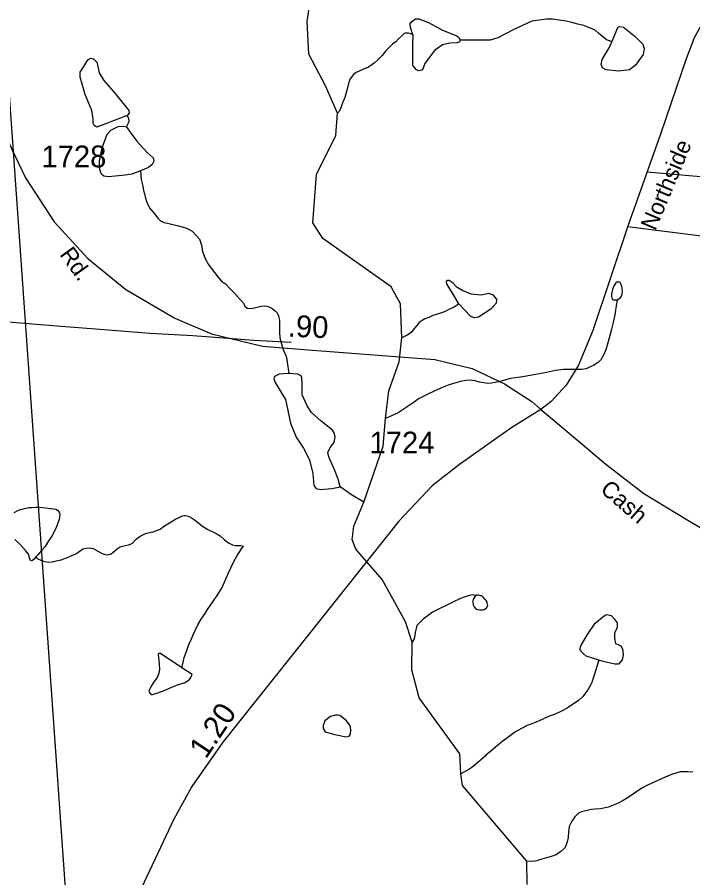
# Model space of a CAD drawing. Extents: x 2056842 to 2160602, y 826753 to 1016856.
# Drawn here: x 2079610 to 2083484, y 850234 to 855171 of the extents above; entities that cross this region are included whole.
import ezdxf

# ---------------------------------------------------------------- set-up
doc = ezdxf.new("R2010")
doc.units = 0
for name, color, linetype in [('Exist Hydrographic Creek Single Shore', 7, 'Continuous'), ('Exist Hydrographic Misc Water Feature', 7, 'Continuous'), ('Exist Railroad Mainline', 7, 'Continuous'), ('Exist Road Non-System Type 51', 7, 'Continuous'), ('Exist Road Secondary Mileage Hundredths English Label', 7, 'Continuous'), ('Exist Road Secondary Type 51 Attributed', 7, 'Continuous'), ('Exist Road Secondary Type 51 Label', 7, 'Continuous'), ('Exist Road Secondary Type 51 Number Label', 7, 'Continuous'), ('Exist Utilities Electrical Transmission Line', 7, 'Continuous')]:
    doc.layers.add(name, color=color, linetype=linetype)

msp = doc.modelspace()

# ---------------------------------------------------------------- linework, layer by layer
at = {"layer": 'Exist Hydrographic Creek Single Shore'}
msp.add_lwpolyline([(2082533.2, 850195.2), (2082532.2, 850329.7), (2082164, 850762.4), (2082153.5, 850829.6), (2082147.3, 850944.7), (2081915.7, 851265.3), (2081872.8, 851426.8), (2081874.3, 851585.1), (2081836.3, 851702.5), (2081702.4, 851944.7), (2081551.4, 852119.8), (2081531.6, 852175.2), (2081540.8, 852250.2), (2081597.5, 852388.6), (2081708.3, 852709.1), (2081722.5, 852867.7), (2081741.3, 853026.8), (2081799.4, 853192.9), (2081816.1, 853331), (2081808, 853526.1), (2081754, 853623.7), (2081363.2, 853900.8), (2081305.4, 853990.6), (2081325.6, 854269.1), (2081436.2, 854493.2), (2081446.4, 854621.1), (2081377.4, 854776.6), (2081283.1, 854958.6), (2081272.6, 855145.8), (2081292.3, 855273.8)], dxfattribs=at)
at = {"layer": 'Exist Hydrographic Misc Water Feature'}
for points in [[(2081879, 855070.5), (2081864.7, 855112.1), (2081863.4, 855133.2), (2081872.6, 855146.4), (2081893.7, 855162.2), (2081912.1, 855162.2), (2081968.8, 855141.1), (2082049.1, 855096.3), (2082130.8, 855064.7), (2082144, 855052.8), (2082147.9, 855043.6)], [(2083018.7, 855029.1), (2083007, 855035.8), (2082988.8, 855041.8), (2082973, 855053.6), (2082956.6, 855067.8), (2082942.4, 855079.6), (2082926.6, 855093.8), (2082906.6, 855103.8), (2082882.6, 855113.5), (2082858.4, 855123.3), (2082824.3, 855131.2), (2082790.5, 855141.3), (2082758.5, 855149), (2082718.3, 855153), (2082678.5, 855159), (2082644.5, 855158.9), (2082604.3, 855154.8), (2082560.4, 855148.5), (2082458.2, 855100.3), (2082366, 855052.8), (2082321.2, 855038.3), (2082214.5, 855039.6), (2082149.2, 855038.3)], [(2083018.7, 855029.1), (2083052.9, 855112.1), (2083066.1, 855117.4), (2083087.2, 855113.5), (2083153, 855059.4), (2083196.5, 855015.9), (2083204.4, 854990.9), (2083199.1, 854956.6), (2083154.4, 854895.9), (2083120.1, 854868.3), (2083058.2, 854861.7), (2082987, 854869.6), (2082966, 854881.4), (2082958, 854899.9), (2082964.6, 854928.9), (2083004.2, 854994.8), (2083018.7, 855029.1)], [(2081880.9, 855069.3), (2081879, 855070.5), (2081866.7, 855076.4), (2081853, 855080.1), (2081836.8, 855080.1), (2081828.8, 855078.1), (2081813, 855062.2), (2081796.8, 855046), (2081780.8, 855030.2), (2081762.8, 855015.9), (2081743.3, 854997.7), (2081721.4, 854975.9), (2081703.3, 854951.8), (2081679.3, 854927.9), (2081657.2, 854907.7), (2081623.5, 854883.6), (2081591.8, 854871.4), (2081553.4, 854853.3), (2081537.8, 854841.4), (2081519.4, 854817.4), (2081511.6, 854799.1), (2081505.6, 854773.2), (2081498.1, 854745.2), (2081488, 854711), (2081475.9, 854679.2), (2081464.4, 854645.2), (2081454, 854628.9), (2081446.4, 854621.1)], [(2082147.9, 855043.6), (2082149.2, 855038.3), (2082146.6, 855029.1), (2082133.4, 855023.8), (2082090, 855021.2), (2082047.8, 855013.3), (2082003, 854979), (2081947.7, 854905.2), (2081933.2, 854868.3), (2081914.7, 854863), (2081898.9, 854869.6), (2081879.2, 854893.3), (2081879.2, 855014.6), (2081880.9, 855069.3)], [(2080241.4, 854606.7), (2080180.8, 854584.3), (2080092.5, 854550), (2080066.2, 854540.8), (2080051.7, 854548.7), (2080046.4, 854561.9), (2080046.4, 854586.9), (2080037.2, 854635.7), (2079999, 854726.7), (2079971.3, 854826.9), (2079971.3, 854855.9), (2079992.4, 854888.8), (2080016.1, 854925.7), (2080033.3, 854935), (2080047.7, 854932.3), (2080066.2, 854912.6), (2080080.7, 854851.9), (2080107, 854807.1), (2080159.7, 854746.4), (2080203.2, 854695), (2080250.6, 854635.7), (2080252, 854621.2), (2080241.4, 854606.7)], [(2080236.1, 854542.6), (2080252, 854572.4), (2080249.3, 854589.6), (2080241.4, 854606.7)], [(2080317.8, 854289.5), (2080267.8, 854271.1), (2080229.6, 854264.5), (2080133.4, 854255.3), (2080107, 854259.2), (2080093.9, 854269.8), (2080083.3, 854296.1), (2080082, 854344.9), (2080096.5, 854421.4), (2080125.5, 854499.1), (2080146.6, 854522.9), (2080190, 854544), (2080219, 854545.3), (2080236.1, 854542.6)], [(2080236.1, 854542.6), (2080258.5, 854511), (2080296.7, 854459.6), (2080356, 854395), (2080389, 854363.4), (2080394.2, 854344.9), (2080383.7, 854326.5), (2080362.6, 854309.3), (2080317.8, 854289.5)], [(2080317.8, 854289.5), (2080321.8, 854239.4), (2080329.9, 854201.7), (2080333.8, 854177.5), (2080339.9, 854157.6), (2080346.1, 854133.5), (2080354.1, 854109.6), (2080368.2, 854077.8), (2080386.3, 854056), (2080397.9, 854042), (2080416, 854017.8), (2080432.6, 854001.9), (2080450.2, 853993.9), (2080472.2, 853990.2), (2080510.5, 853980.4), (2080534.1, 853974.3), (2080556.7, 853968.5), (2080580.2, 853960.4), (2080600.7, 853950.4), (2080614.3, 853942.7), (2080638.9, 853916.6), (2080654.7, 853896.8), (2080668.8, 853856.5)], [(2080668.8, 853856.5), (2080669, 853852.8), (2080672.7, 853826.7), (2080688.9, 853782.9), (2080707.2, 853752.9), (2080723.2, 853731), (2080761.1, 853681), (2080781.4, 853656.9), (2080805.4, 853641.1), (2080833.7, 853611.2), (2080855.6, 853587.2), (2080885.6, 853555.5), (2080907.5, 853529.4), (2080915.5, 853513.6), (2080929.6, 853501.7), (2080945.8, 853499.7), (2080962, 853501.7), (2080986, 853507.8), (2081009.8, 853513.9), (2081026, 853515.9), (2081041.8, 853513.9), (2081057.8, 853507.9), (2081071.7, 853500), (2081092, 853484), (2081099.8, 853474.3), (2081108, 853458), (2081114.2, 853430.3), (2081114.2, 853400.3), (2081114.2, 853364.2), (2081116.4, 853332.2), (2081126.5, 853290.1), (2081136.3, 853258.2), (2081148.6, 853234.4), (2081154.4, 853218.5), (2081166.7, 853127.4)], [(2082143, 853527.3), (2082112.5, 853577.5), (2082073, 853640.8), (2082071.6, 853655.3), (2082078.2, 853663.2), (2082087.5, 853663.2), (2082104.6, 853650.1), (2082127, 853626.3), (2082165.2, 853603.9), (2082211.3, 853584.1), (2082270.6, 853577.5), (2082314.1, 853586.8), (2082336.5, 853577.5), (2082358.9, 853553.8), (2082356.2, 853530.1), (2082325.9, 853495.8), (2082254.8, 853449.7), (2082229.7, 853445.7), (2082208.7, 853456.3), (2082143, 853527.3)], [(2083049.3, 853550), (2083053.6, 853552.2), (2083061.4, 853556.3), (2083069.2, 853562.4), (2083075.3, 853570.4), (2083079.4, 853582.4), (2083079, 853588.5), (2083081.3, 853598.3), (2083079, 853614), (2083077.4, 853626.1), (2083072.9, 853638.1), (2083071, 853642.1), (2083066.9, 853648.4), (2083063, 853650.2), (2083055, 853650.2), (2083051.1, 853650.3), (2083046.8, 853650.2), (2083043.3, 853646.3), (2083039.2, 853642), (2083033.3, 853632), (2083027.1, 853620.3), (2083023.2, 853608.3), (2083019.3, 853594.3), (2083017.3, 853580), (2083017.5, 853568.2), (2083019.1, 853560.3), (2083021.6, 853554.2), (2083025.5, 853552), (2083029.4, 853550.2), (2083039.6, 853550.3), (2083049.3, 853550)], [(2083049.3, 853550), (2083045.8, 853528.2), (2083037.6, 853464.1), (2083031.6, 853438.3), (2083025.9, 853412), (2083018.1, 853380.3), (2083008.3, 853344), (2082996.2, 853302), (2082986.3, 853268.2), (2082974.4, 853235.9), (2082956.4, 853205.8), (2082940.4, 853190), (2082916.6, 853173.7), (2082890.6, 853163.8), (2082872.3, 853153.6), (2082848.2, 853150.6), (2082788.9, 853150.6), (2082741.5, 853150.6), (2082696.8, 853143.3), (2082644, 853132.1), (2082582, 853120.2), (2082509.6, 853107.1), (2082438.6, 853098.5), (2082404.6, 853088.2), (2082371, 853079.9), (2082328.9, 853072.1), (2082306.8, 853069.8), (2082285, 853073.9), (2082261.1, 853077.9), (2082235.2, 853083.9), (2082206.9, 853087.7), (2082182.7, 853087.4), (2082151.1, 853081.6), (2082111, 853069.5), (2082081.2, 853059.3), (2082043.1, 853045.2), (2082005.1, 853027), (2081957.4, 853004.7), (2081911.2, 852980.8), (2081885.4, 852962.8), (2081857.7, 852942.7), (2081795, 852901.9), (2081722.5, 852867.7)], [(2082143, 853527.3), (2082127.8, 853515.3), (2082111.6, 853505.1), (2082088, 853495.3), (2082059.5, 853481), (2082032, 853470.9), (2081993.9, 853458.9), (2081970.1, 853448.7), (2081947.9, 853440.7), (2081931.7, 853430.9), (2081915.7, 853418.8), (2081902, 853402.6), (2081887.9, 853386.5), (2081880.3, 853376.6), (2081870.2, 853364.4), (2081855.9, 853352.4), (2081846.4, 853346.5), (2081816.1, 853331)], [(2081166.7, 853127.4), (2081111.3, 853123.4), (2081086.3, 853110.2), (2081082.4, 853097), (2081088.9, 853074.6), (2081148.2, 852977.1), (2081162.7, 852915.1), (2081177.2, 852841.3), (2081210.2, 852762.2), (2081252.3, 852698.9), (2081286.6, 852630.8), (2081305, 852553), (2081311.6, 852484.4), (2081324.8, 852467.3), (2081348.5, 852460.7), (2081414.4, 852467.3), (2081461.8, 852475.7)], [(2081461.8, 852475.7), (2081451.3, 852521.4), (2081430.2, 852574.1), (2081397.2, 852647.9), (2081392, 852673), (2081403.8, 852702), (2081427.5, 852731), (2081434.1, 852763.9), (2081430.2, 852782.4), (2081417, 852800.8), (2081353.8, 852853.6), (2081298.4, 852902.3), (2081272.1, 852941.9), (2081244.4, 853003.8), (2081243.1, 853069.8), (2081241.8, 853102.7), (2081237.8, 853112.9), (2081219.4, 853123.4), (2081166.7, 853127.4)], [(2081597.5, 852388.6), (2081526.3, 852430.9), (2081461.8, 852475.7)], [(2079593.5, 852329.6), (2079617.5, 852341.8), (2079651.6, 852351.6), (2079677.6, 852357.8), (2079695.4, 852357.9), (2079715.3, 852359.8), (2079737.5, 852360.1), (2079753.3, 852358.1), (2079773.4, 852356.3), (2079801.7, 852352), (2079819.5, 852350.1), (2079831.6, 852348.3), (2079841.6, 852342.3), (2079851.5, 852330.3), (2079853.7, 852320.2), (2079853.5, 852304.4), (2079851.7, 852288.4), (2079843.7, 852268.1), (2079830, 852234.1), (2079808, 852194), (2079790.2, 852166.3), (2079770.3, 852134), (2079750.2, 852111.9), (2079726.4, 852083.8), (2079716.1, 852074)], [(2079716.1, 852074), (2079728.5, 852064), (2079746.3, 852056), (2079766.6, 852048.1), (2079792.4, 852044.2), (2079810.7, 852046.3), (2079834.5, 852052.5), (2079862.8, 852058.3), (2079902.5, 852072.6), (2079920.4, 852080.4), (2079946.6, 852092.7), (2079958.1, 852100.6), (2079986.2, 852120.7), (2080006.5, 852125), (2080022.5, 852127), (2080046.5, 852122.9), (2080072.3, 852106.9), (2080098, 852093.2), (2080114.4, 852089.1), (2080128.5, 852087), (2080138.1, 852089.2), (2080148.2, 852091.3), (2080158, 852099.5), (2080184.3, 852121.5), (2080200.1, 852131.4), (2080214.2, 852135.3), (2080247.8, 852143.6), (2080260.2, 852147.8), (2080270.4, 852153.6), (2080289.9, 852173.7), (2080304.2, 852185.7), (2080320, 852195.9), (2080337.7, 852205.8), (2080353.7, 852209.9), (2080377.6, 852216), (2080390, 852218.2), (2080404.1, 852224.1), (2080429.9, 852234), (2080453.9, 852252.3), (2080483.7, 852270.1), (2080517.5, 852290.5), (2080541.7, 852302.3), (2080557.9, 852310.4), (2080567.5, 852312.6), (2080573.5, 852312.5), (2080583.3, 852310.6), (2080595.4, 852306.7), (2080609.6, 852298.9), (2080631.9, 852282.9), (2080671.7, 852251), (2080703.7, 852231.1), (2080751.9, 852209.2), (2080773.6, 852195.3), (2080798, 852173.3), (2080821.8, 852155.6), (2080844.1, 852143.7), (2080862.2, 852139.7), (2080890.3, 852139.5), (2080908.3, 852135.6)], [(2079716.1, 852074), (2079708.6, 852063.8), (2079698.3, 852054), (2079692.6, 852052.1), (2079684.6, 852055.7), (2079680.7, 852069.7), (2079674.1, 852089.7), (2079660.6, 852109.7), (2079642.3, 852127.8), (2079624.3, 852149.7), (2079596.4, 852173.7)], [(2080554.2, 851438.6), (2080558.1, 851452.6), (2080564.2, 851478.8), (2080568.1, 851496.5), (2080581.9, 851536.6), (2080594, 851572.5), (2080609.8, 851604.6), (2080619.8, 851626.6), (2080631.5, 851652.9), (2080645.2, 851684.9), (2080665.1, 851717.1), (2080687.5, 851749), (2080701.2, 851772.9), (2080731.2, 851817.1), (2080761.1, 851859.2), (2080784.7, 851899.4), (2080802.9, 851939.3), (2080822.6, 851983.4), (2080852.3, 852047.4), (2080870, 852079.7), (2080896, 852121.6), (2080900.1, 852127.5), (2080908.3, 852135.6)], [(2082243.4, 851854.1), (2082238.1, 851852.6), (2082219.4, 851856.1), (2082195.4, 851852.1), (2082173.7, 851844), (2082151.6, 851836), (2082111.6, 851817.7), (2082073.6, 851797.5), (2082029.8, 851775.7), (2081991.8, 851757.5), (2081966, 851737.6), (2081939.9, 851719.1), (2081922.1, 851701.2), (2081902.2, 851681.1), (2081897.9, 851663.1), (2081892.2, 851641.2), (2081890.5, 851623.2), (2081886.2, 851605.2), (2081874.3, 851585.1)], [(2082243.4, 851854.1), (2082238.1, 851852.6), (2082231.5, 851844.2), (2082225.6, 851834.1), (2082223.7, 851827.9), (2082221.3, 851816.1), (2082223.7, 851810), (2082223.7, 851800.3), (2082229.9, 851788), (2082237.5, 851778.4), (2082243.6, 851774.2), (2082251.8, 851772.1), (2082260, 851770.1), (2082267.6, 851770.5), (2082277.9, 851770.2), (2082287.5, 851772.4), (2082293.7, 851776.3), (2082299.6, 851778.3), (2082305.6, 851788.3), (2082307.8, 851794.5), (2082305.3, 851808.2), (2082305.6, 851814.3), (2082299.6, 851824.5), (2082293.5, 851830.3), (2082281.6, 851844.3), (2082273.8, 851850.3), (2082267.2, 851852.1), (2082255.3, 851854.4), (2082243.4, 851854.1)], [(2082944, 851482.2), (2082872.8, 851505.9), (2082853, 851521.7), (2082838.6, 851540.2), (2082839.9, 851560), (2082880.7, 851628.5), (2082924.2, 851694.4), (2082978.2, 851739.2), (2082991.4, 851743.2), (2083016.4, 851737.9), (2083033.5, 851719.5), (2083050.7, 851695.7), (2083050.7, 851669.4), (2083034.9, 851637.7), (2083034.9, 851607.4), (2083041.4, 851577.1), (2083059.9, 851569.2), (2083070.4, 851563.9), (2083079.7, 851546.8), (2083083.6, 851512.5), (2083078.3, 851484.8), (2083057.3, 851458.4), (2083036.2, 851458.4), (2082970.3, 851474.3), (2082944, 851482.2)], [(2080554.2, 851438.6), (2080432.2, 851520.4), (2080427.9, 851520.2), (2080421.9, 851520.3), (2080417.8, 851516), (2080418.2, 851510.3), (2080421.9, 851482.2), (2080424.2, 851456.3), (2080426.7, 851428.3), (2080422.6, 851408.2), (2080416.4, 851390.1), (2080406.6, 851374.1), (2080392.6, 851354.3), (2080382.8, 851338), (2080374.8, 851326.2), (2080369, 851314.1), (2080364.9, 851302.1), (2080366.8, 851298.2), (2080374.8, 851288), (2080380.9, 851285.9), (2080386.5, 851284.2), (2080416.6, 851294.3), (2080452.5, 851308.3), (2080496.4, 851326.4), (2080528.6, 851340.6), (2080572.4, 851354.7), (2080586.6, 851362.7), (2080598.5, 851370.6), (2080606.5, 851382.8), (2080612.2, 851396.9), (2080614.1, 851400.7), (2080554.2, 851438.6)], [(2082944, 851482.2), (2082904.5, 851354.1), (2082897.9, 851338.1), (2082882.2, 851312.1), (2082870.3, 851296), (2082852.4, 851273.9), (2082826.6, 851247.9), (2082782.7, 851219.6), (2082762.8, 851207.6), (2082730.8, 851189.3), (2082695.1, 851173.2), (2082656.6, 851159.2), (2082620.9, 851141.1), (2082577, 851123), (2082533.2, 851106.9), (2082501.2, 851090.7), (2082463, 851068.5), (2082431.4, 851044.4), (2082395.2, 851018.3), (2082365.2, 850994.4), (2082323.6, 850958.1), (2082299.8, 850938.2), (2082291.6, 850930.1), (2082237.7, 850883.9), (2082215.9, 850866.1), (2082199.9, 850853.9), (2082153.5, 850829.6)], [(2081435.1, 851166.7), (2081407.1, 851158.9), (2081374.5, 851133.5), (2081363.5, 851108), (2081363.5, 851089.2), (2081375.8, 851070.9), (2081430.5, 851055.9), (2081496.3, 851042.9), (2081512.6, 851046.8), (2081521, 851057.9), (2081523.6, 851083.3), (2081519.1, 851106.7), (2081495.6, 851136.1), (2081460.5, 851164.1), (2081448.8, 851167.3), (2081435.1, 851166.7)], [(2083484, 850839.8), (2083453.6, 850841.6), (2083412, 850841.4), (2083367.5, 850827.4), (2083325.7, 850811.5), (2083261.9, 850783), (2083224.2, 850765.2), (2083192.2, 850746.9), (2083150.2, 850718.8), (2083118.4, 850698.9), (2083084.5, 850676.8), (2083056.7, 850662.4), (2083024, 850648.6), (2082998.2, 850638.4), (2082956.4, 850630.1), (2082924.2, 850628.1), (2082900.6, 850626), (2082846.3, 850611.9), (2082828.4, 850604), (2082806.9, 850583.8), (2082790.5, 850557.8), (2082774.9, 850527.7), (2082770.8, 850497.6), (2082769, 850463.8), (2082762.8, 850439.5), (2082751.1, 850407.6), (2082727.1, 850383.6), (2082699.5, 850365.5), (2082665.6, 850353.2), (2082637.5, 850345.3), (2082605.5, 850337.2), (2082589.5, 850331), (2082563.5, 850326.9), (2082532.2, 850329.7)]]:
    msp.add_lwpolyline(points, dxfattribs=at)
at = {"layer": 'Exist Railroad Mainline'}
msp.add_lwpolyline([(2081181.8, 853304.7), (2080967.8, 853316.1), (2080795.7, 853329.8), (2080617.5, 853343.5), (2080371.6, 853357), (2080133.4, 853374.5), (2079837.4, 853397.8), (2079559.3, 853421.3)], dxfattribs=at)
at = {"layer": 'Exist Road Non-System Type 51'}
for points in [[(2083221.3, 854283.4), (2083616.1, 854250), (2084368, 854196), (2084772, 854159.6), (2084904.9, 854153.4), (2085102.2, 854261.5), (2085249.7, 854267.7), (2085380.6, 854238.6), (2085440.8, 854246.9), (2085509.3, 854224.1), (2085586.2, 854190.8)], [(2083109.9, 853969.7), (2083533.1, 853917.5), (2083605.8, 853888.4), (2083626.5, 853842.7), (2083624.4, 853759.5), (2083599.5, 853649.4), (2083599.5, 853599.5), (2083653.5, 853568.3)]]:
    msp.add_lwpolyline(points, dxfattribs=at)
at = {"layer": 'Exist Road Secondary Type 51 Attributed'}
for points in [[(2087449.7, 857409.9), (2087040.5, 857169.9), (2086532.2, 856865.9), (2086157.3, 856642.3), (2085516.1, 856263.7), (2085113.7, 856080.3), (2084712.8, 855964.9), (2084408, 855887.5), (2084270.9, 855828.3), (2084122.4, 855729.6), (2083844.7, 855515), (2083712.8, 855397.5), (2083612.6, 855268.2), (2083491.1, 855053), (2083445.4, 854932.5), (2083298.4, 854500.7), (2083113.1, 853978.5), (2082911.1, 853374.3), (2082828.5, 853174.2), (2082757.9, 853058.9), (2082670.7, 852966.4), (2082612.5, 852919.6)], [(2079112.9, 855248.1), (2079221.6, 855119.8), (2079309.3, 854976.9), (2079389.3, 854833.5), (2079451.6, 854689.1), (2079577.8, 854418.4), (2079657.8, 854249), (2079822.4, 853997), (2080014.5, 853787), (2080233.1, 853607.8), (2080513.5, 853443.6), (2080723.7, 853353.7), (2081016.6, 853284.1), (2081253.4, 853264.3), (2081729.5, 853228.5), (2082003.7, 853206.7), (2082219.2, 853156.3), (2082405, 853066.9), (2082561.3, 852965.6), (2082612.5, 852919.6)], [(2082612.5, 852919.6), (2082446.6, 852816.4), (2082145.4, 852604.4), (2081989.6, 852481.8), (2081798.6, 852280.2), (2081276.2, 851624.5), (2080789.2, 851012.4), (2080610.6, 850756.8), (2080508.8, 850569.7), (2080277.2, 850078.2), (2080163, 849773.9), (2080132.8, 849669.4), (2080123.5, 849627.1), (2080070.5, 849339.3), (2080035.2, 849218.7), (2079968.8, 849116.9), (2079875.3, 848998.4), (2079759, 848915.3), (2079640.6, 848869.6), (2079491.1, 848832.2), (2079177.5, 848836.3), (2078779.7, 848824.9)], [(2082612.5, 852919.6), (2082763.6, 852794.4), (2082984.8, 852607.3), (2083202.4, 852438.5), (2083454.7, 852285.7), (2084155.2, 851870.6), (2084318.2, 851764.6), (2084438.1, 851649.7), (2084509.8, 851537.5), (2084548.2, 851426.3), (2084569.5, 851319.8), (2084563.3, 851187.8), (2084529, 851055.8), (2084380, 850696.8), (2084308.3, 850528.5), (2084228.9, 850350.2), (2084199.8, 850245.3), (2084187.4, 850116.4)]]:
    msp.add_lwpolyline(points, dxfattribs=at)
at = {"layer": 'Exist Utilities Electrical Transmission Line'}
msp.add_lwpolyline([(2079289.6, 845905.8), (2079948.4, 849305.4), (2079483.2, 855866.2), (2080101, 858353.8), (2081583.8, 864201.8), (2082616, 868304.1), (2080660.7, 871519), (2079505, 873046.5), (2077150, 875999.6), (2076168.7, 877076.1), (2079417.8, 882691.3), (2077477.1, 888146.6), (2075950.7, 892161.6), (2073748.3, 895216.6), (2070106.7, 900031.7)], dxfattribs=at)

# ---------------------------------------------------------------- texts
at = {"layer": 'Exist Road Secondary Mileage Hundredths English Label'}
for s, rotation, p in [('.90', 357.7309, (2081159.9, 853338.3)), ('1.20', 56.3987, (2080692.5, 850910.9))]:
    msp.add_text(s, height=125, rotation=rotation, dxfattribs=at).set_placement(p)
at = {"layer": 'Exist Road Secondary Type 51 Label'}
for s, rotation, p in [('Northside', 67.2026, (2083268.8, 853941.9)), ('Rd.', 305.636, (2079850.4, 853809.7)), ('Cash', 319.2311, (2082947.4, 852452.2))]:
    msp.add_text(s, height=95, rotation=rotation, dxfattribs=at).set_placement(p)
at = {"layer": 'Exist Road Secondary Type 51 Number Label'}
for s, p in [('1728', (2079749.4, 854309.8)), ('1724', (2081630.2, 852668))]:
    msp.add_text(s, height=125, dxfattribs=at).set_placement(p)

doc.saveas('drawing.dxf')
